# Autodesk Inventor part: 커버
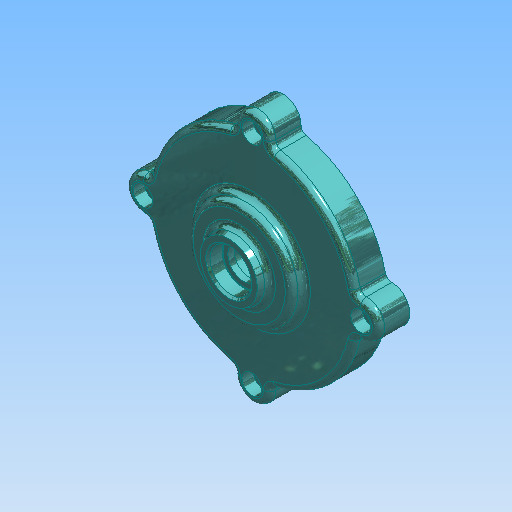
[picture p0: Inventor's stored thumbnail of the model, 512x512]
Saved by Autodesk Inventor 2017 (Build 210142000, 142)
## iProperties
Created: 2021-07
Part Number: 커버
Document SubType Name: 모델링
Designer: mdu
Material: 알루미늄 6061
Density: 2.71 g/cm^3
Mass: 196.657 g
Surface Area: 278.607 cm^2
Volume: 72.5671 cm^3
Appearance: 커버
변환 표준: STEP AP214IS
파일 이름: C:\Users\SeoGD\Desktop\?쒗뿕\而ㅻ쾭-1.stp
전처리기: Build: 253, Release: 2010 SP1 - Date: Wed 07/29/2009
전송 단위: 밀리미터
불확실성: 0.01
Author: mdu
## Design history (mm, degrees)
sketch "스케치1"
  geometry: L1 (0, 0)-(0, 26); L2 (50, 0)-(50, 15); L3 (50, 15)-(25, 15); L4 (25, 15)-(25, 21); L5 (25, 21)-(15, 21); L6 (15, 21)-(13.66, 26); L7 (13.66, 26)-(10, 26); L8 (50, 0)-(45, 0); L9 (45, 0)-(45, 10); L10 (45, 10)-(14.5, 10); L11 (14.5, 10)-(13.266, 3); L12 (13.266, 3)-(11, 3); L13 (11, 3)-(11, 16); L14 (11, 16)-(7.5, 16); L15 (7.5, 16)-(7.5, 19); L16 (7.5, 19)-(10, 19); L17 (10, 19)-(10, 26)
  constraints: 34 end point, 10 parallel, 2 perpendicular, 2 point on line, 1 vertical
  dimensions: "d11" = 100 diameter of L2 L1; "d12" = 22 diameter of L13 L1; "d13" = 90 diameter of L9 L1; "d14" = 15 distance between parallel lines of L3 L8; "d15" = 10 distance between parallel lines of L8 L10; "d16" = 29 diameter of L10.end L1; "d17" = 100 deg angle of L11 L10; "d18" = 7 distance between parallel lines of L12 L10; "d19" = 13 distance between parallel lines of L14 L12; "d20" = 3 distance between parallel lines of L16 L14; "d21" = 15 diameter of L15 L1; "d22" = 20 diameter of L17 L1; "d23" = 30 diameter of L5.end L1; "d24" = 6 distance between parallel lines of L5 L3; "d25" = 50 diameter of L4 L1; "d26" = 105 deg angle of L5 L6; "d50" = 26 distance of L1.start L1.end
revolve "회전1" sketch "스케치1" stored, may be unused: angle "d27" = 90 deg
sketch "스케치2" dims "d29" = 104
  geometry: A1 r 8.5 centre (0, 52) between (8.074, 49.344) and (-8.074, 49.344); A2 r 50 centre (0, 0) between (-8.074, 49.344) and (8.074, 49.344) reference; 2 further points
  constraints: 4 point on circle, 2 vertical alignment, 1 centre point, 1 coincident, 2 other
  dimensions: "d28" = 17 diameter of A1
extrude "돌출1" join sketch "스케치2" stored distance "d30" = 10; taper "d31" = 0 deg
fillet "모깎기3" dims "d32" = 3
fillet "모깎기4" dims "d45" = 3, "d46" = 0.2
chamfer "모따기1" distance "d47" = 1; stored, may be unused: second distance "d48" = 2, angle "d49" = 45 deg
hole "구멍2" diameter "d38" = 5.5; stored, may be unused: countersink angle "d42" = 90 deg, drill point angle "d44" = 118 deg; dims "d36" = 10, "d37" = 10, "d39" = 6, "d40" = 9.5, "d41" = 5.4, "d43" = 8
node "솔리드1"
node "솔리드 본체"
node "곡면 본체"
pattern_circular "원형 패턴1" dims angle "d34" = 360 deg
pattern_circular "원형 패턴2" dims angle "d52" = 360 deg
node "솔리드2"
